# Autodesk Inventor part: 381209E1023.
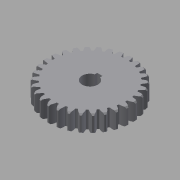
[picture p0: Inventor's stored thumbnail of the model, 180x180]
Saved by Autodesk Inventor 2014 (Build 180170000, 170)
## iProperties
Created: 2018-12
Part Number: 381209E1023.
Material: Generic
Document SubType Name: Modeling
Designer: kh
Density: 1 g/cm^3
Appearance: Default
Author: kh
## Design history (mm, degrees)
sketch "Sketch1" dims "d1" = 2.5 (= 1.25 x d0), "d2" = 60 (= 30 x d0)
  geometry: L1 (0, 0)-(0, 32); L2 (0, 0)-(-23.779, 0); L3 (-2.07, 0)-(-2.07, 27.422); L4 (-1.57, 0)-(-1.57, 29.959); L5 (-0.57, 0)-(-0.57, 31.995); L6 (2.07, 0)-(2.07, 27.422); L7 (1.57, 0)-(1.57, 29.959); L8 (0.57, 0)-(0.57, 31.995); L9 (-0.57, 31.995)-(0.57, 31.995); A1 r 32 centre (0, 0) between (0, 32) and (-0.57, 31.995); A2 r 9.292 centre (7.208, 26.911) between (-0.57, 31.995) and (-2.07, 27.422); A3 r 9.292 centre (-7.208, 26.911) between (2.07, 27.422) and (0.57, 31.995); A4 r 27.5 centre (0, 0) between (-2.07, 27.422) and (2.07, 27.422); 2 further points
  constraints: 18 end point, 10 point on circle, 7 symmetric about line, 4 centre point, 4 coincident, 3 perpendicular, 3 point on line, 2 parallel, 1 vertical, 7 other
  dimensions: "d0" = 2 dimension on A1; "d3" = 0.5 distance between parallel lines of L4 L3 (= 0.25 x d0); "d4" = 1 distance between parallel lines of L5 L4 (= 0.5 x d0); "d5" = 1.57 distance between parallel lines of L1 L4 (= 0.785 x d0)
extrude "Extrusion1" new body sketch "Sketch1" distance "d6" = 13; taper "d7" = 0 deg
chamfer "Chamfer1" distance "d8" = 1; stored, may be unused: second distance "d9" = 2, angle "d10" = 45 deg
fillet "Fillet1" dims "d11" = 0.5
sketch "Sketch2"
  geometry: L1 (-2, 7.5)-(2, 7.5); L2 (2, 7.5)-(2, 0); L3 (2, 0)-(-2, 0); L4 (-2, 0)-(-2, 7.5); C1 r 6 at (0, 0); 2 further points
  constraints: 8 end point, 2 coincident, 2 parallel, 1 centre point, 1 horizontal, 1 midpoint, 1 perpendicular
  dimensions: "d15" = 12 diameter of C1; "d16" = 4 distance of L1.start L1.end; "d17" = 13.5 dimension on C1 L1
extrude "Extrusion2" cut sketch "Sketch2" stored distance "d18" = 13; taper "d19" = 0 deg
body "Solid1"
pattern_circular "Circular Pattern1" dims "d13" = 360 deg
